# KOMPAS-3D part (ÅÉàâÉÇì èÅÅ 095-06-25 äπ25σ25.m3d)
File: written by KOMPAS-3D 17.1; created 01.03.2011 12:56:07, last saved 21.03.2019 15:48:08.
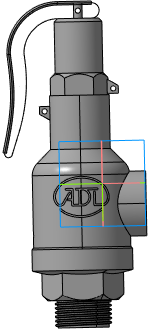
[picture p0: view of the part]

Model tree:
1. Операция без истории:1

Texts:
  Viktor2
